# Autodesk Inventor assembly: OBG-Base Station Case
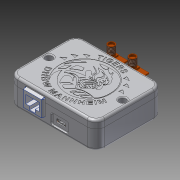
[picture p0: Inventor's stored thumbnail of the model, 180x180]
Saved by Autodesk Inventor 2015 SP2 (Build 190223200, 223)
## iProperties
Created: 2014-11
Part Number: OBG-Base Station Case
Document SubType Name: Assembly
Designer: rYan
Author: rYan
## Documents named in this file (5)
- E:\Tigers SVN\mechanik\2016\Inventor\Gehäuse\OBG-Base Station Case.iam
- E:\Tigers SVN\mechanik\2016\Inventor\Gehäuse\Base Station Case Bottom.ipt
- E:\Tigers SVN\mechanik\2016\Inventor\Elektronik\MG-Base Station V2.iam
- E:\Tigers SVN\mechanik\2016\Inventor\Inhaltscenter\de-DE\ISO 4762(1)\ISO 4762 - M3 x 6DIN EN ISO.ipt
- E:\Tigers SVN\mechanik\2016\Inventor\Gehäuse\Base Station Case Top.ipt
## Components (9 placed, 4 different names)
1. Base Station Case Bottom:1 — Passend:1, Passend:2, Passend:3, Passend:6, Fluchtend:1, Fluchtend:2
2. MG-Base Station V2:1 [sub-assembly] — Passend:1, Passend:2, Passend:3, Passend:5
3. Base Station Case Top:1 — Passend:6, Fluchtend:1, Fluchtend:2, Passend:8, Passend:10
4. DIN EN ISO 4762 M3 x 6:5 — Passend:8
5. DIN EN ISO 4762 M3 x 6:6 — Passend:10
6. DIN EN ISO 4762 M3 x 6:1 — Passend:5
7. DIN EN ISO 4762 M3 x 6:2
8. DIN EN ISO 4762 M3 x 6:3
9. DIN EN ISO 4762 M3 x 6:4
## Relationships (9: Mate 7, Flush 2)
- Passend:1 [Mate]: Base Station Case Bottom:1 ↔ MG-Base Station V2:1
- Passend:2 [Mate]: Base Station Case Bottom:1 ↔ MG-Base Station V2:1
- Passend:3 [Mate]: Base Station Case Bottom:1 ↔ MG-Base Station V2:1
- Passend:5 [Mate]: MG-Base Station V2:1 ↔ DIN EN ISO 4762 M3 x 6:1
- Passend:6 [Mate]: Base Station Case Bottom:1 ↔ Base Station Case Top:1
- Fluchtend:1 [Flush]: Base Station Case Bottom:1 ↔ Base Station Case Top:1
- Fluchtend:2 [Flush]: Base Station Case Bottom:1 ↔ Base Station Case Top:1
- Passend:8 [Mate]: Base Station Case Top:1 ↔ DIN EN ISO 4762 M3 x 6:5
- Passend:10 [Mate]: Base Station Case Top:1 ↔ DIN EN ISO 4762 M3 x 6:6
